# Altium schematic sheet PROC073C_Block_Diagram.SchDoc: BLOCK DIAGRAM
size 431 x 279 mm; Date: Not shown in title block; ApprovedBy: Not shown in title block; CheckedBy: Not shown in title block; Author: Not shown in title block; CompanyName: Not shown in title block; DrawnBy: Charles F. Oladimeji; Engineer: Not shown in title block; Organization: Not shown in title block; Address1: Not shown in title block; Address2: Not shown in title block; Address3: Not shown in title block; Address4: Not shown in title block; DocumentNumber: 1; Revision: Use project parameter SCH_Rev; SheetNumber: 1; SheetTotal: 13; PageSetup: Record=PageOptions¦CenterHorizontal=True¦CenterVertical=True¦PrintScale=1.00¦XCorrection=1.00¦YCorrection=1.00¦PrintKind=0¦BorderSize=5000000¦LeftOffset=0¦BottomOffset=0¦Orientation=2¦PaperLength=1000¦PaperWidth=1000¦Scale=100¦PaperSource=15¦PrintQuality=600¦MediaType=1¦DitherType=10¦PaperKind=Letter¦PrintScaleMode=1
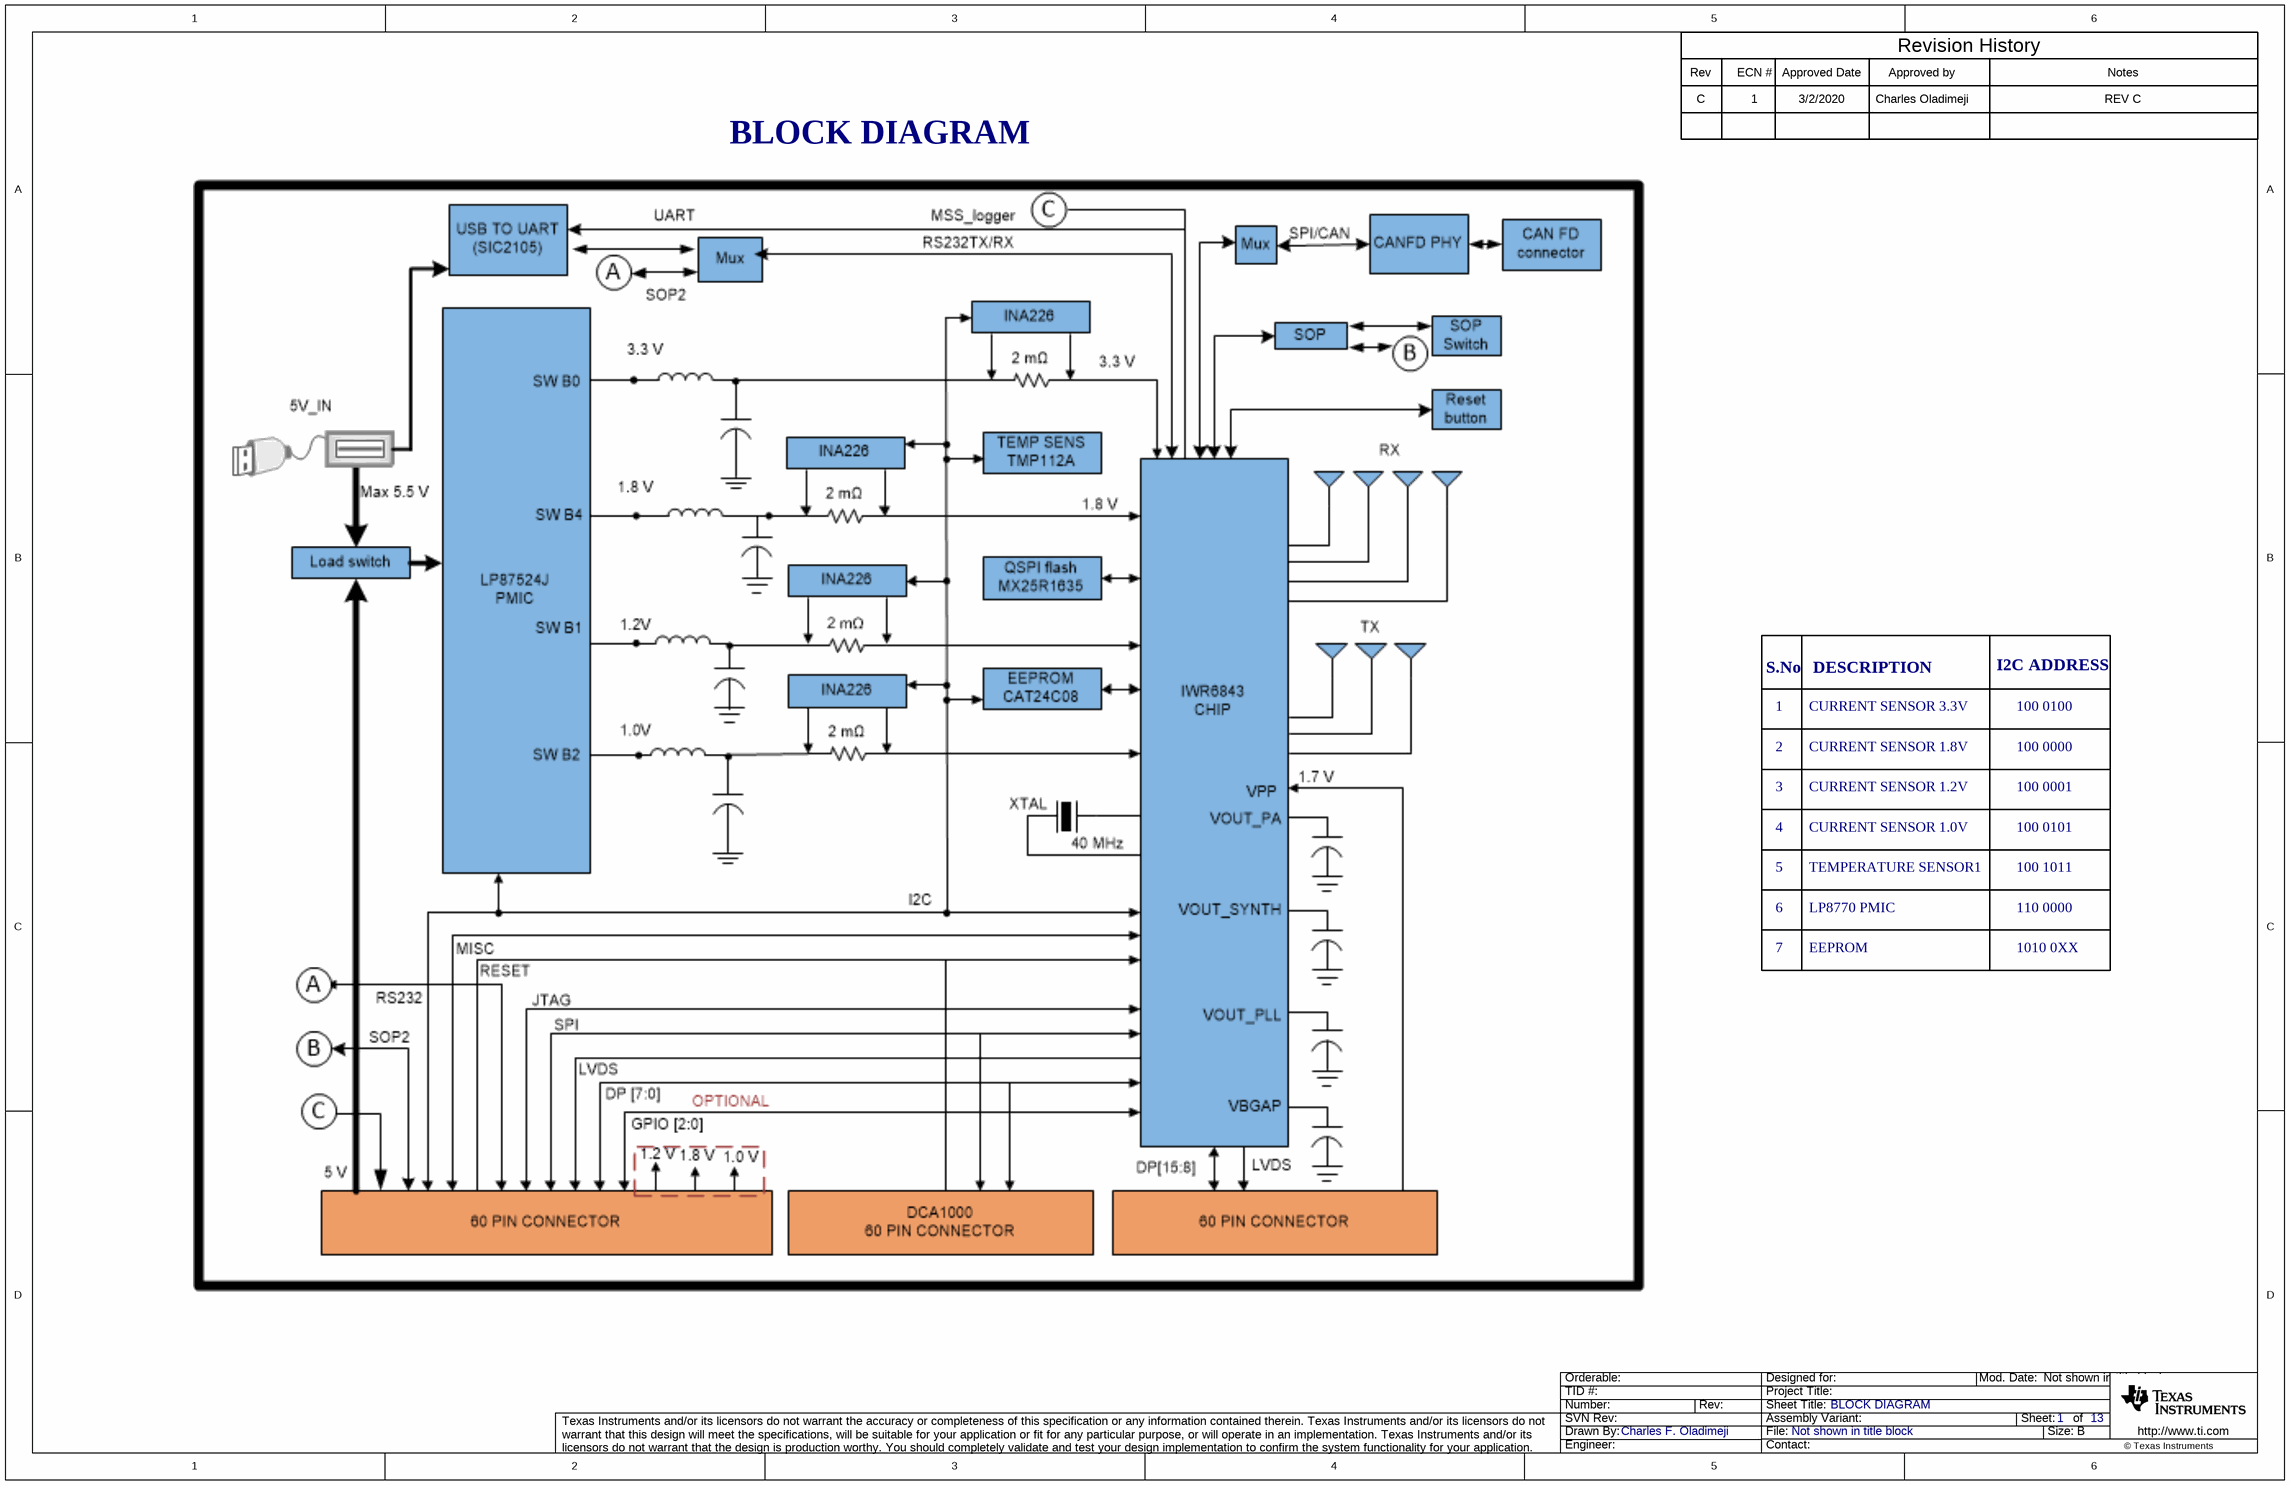
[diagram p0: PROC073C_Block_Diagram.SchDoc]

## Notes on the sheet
- Rev
- C
- ECN #
- 1
- Approved Date
- 3/2/2020
- Approved by
- Charles Oladimeji
- Revision History
- Notes
- REV C
- BLOCK DIAGRAM
- S.No
- DESCRIPTION
- I2C ADDRESS
- 2
- CURRENT SENSOR 3.3V
- CURRENT SENSOR 1.8V
- 100 0100
- 100 0000
- 3
- 4
- CURRENT SENSOR 1.2V
- CURRENT SENSOR 1.0V
- 100 0001
- 100 0101
- 5
- TEMPERATURE SENSOR1
- 100 1011
- 6
- 7
- LP8770 PMIC
- EEPROM
- 1010 0XX
- 110 0000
